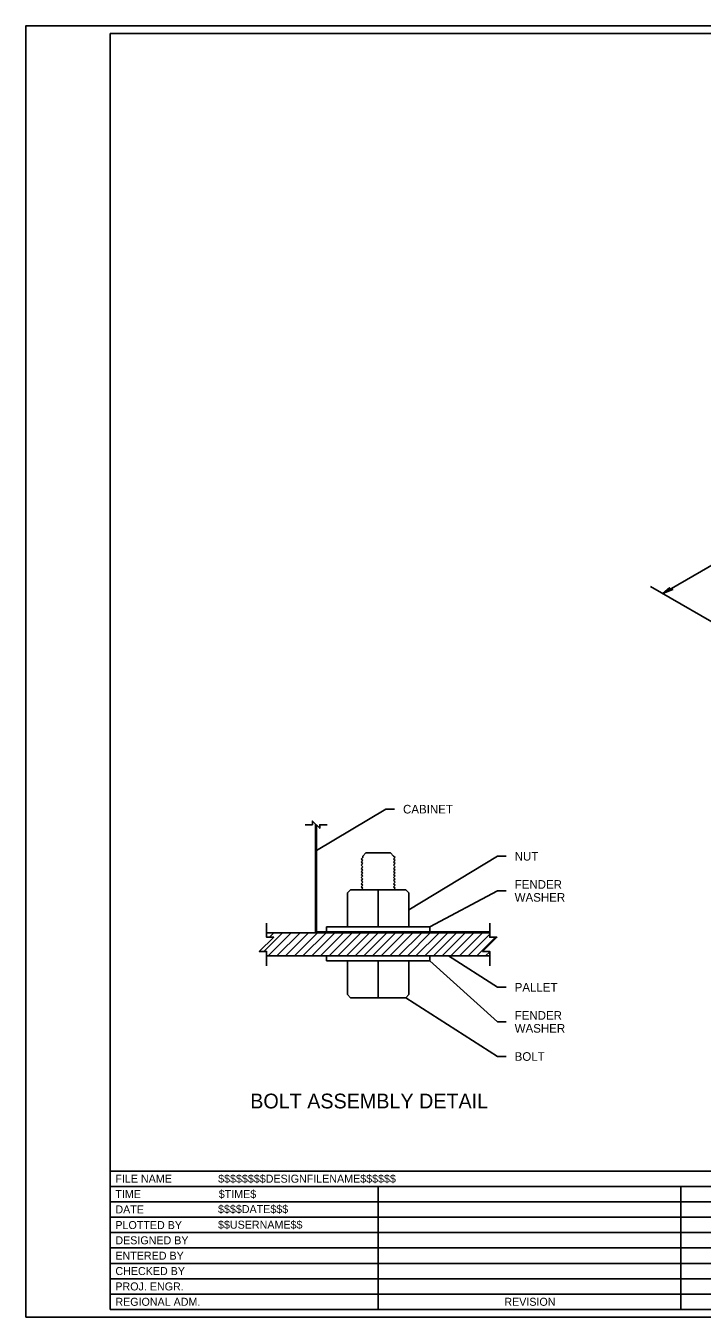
# Model space of a CAD drawing. Extents: x 99988 to 100172, y 99995 to 100047.
# Drawn here: x 99999.31 to 100004.81, y 99999.94 to 100010.44 of the extents above; entities that cross this region are included whole.
import ezdxf

# ---------------------------------------------------------------- set-up
doc = ezdxf.new("R2010")
doc.units = 0
for name, color, linetype in [('Level 1', 7, 'Continuous'), ('Level 15', 7, 'Continuous'), ('Level 2', 7, 'Continuous'), ('Level 20', 7, 'Continuous'), ('SH_GI_PlotLimits', 7, 'Continuous'), ('SH_GI_SheetBorder', 7, 'Continuous'), ('SH_GI_SheetTextInCells', 7, 'Continuous'), ('SH_GI_TitleBlockText', 7, 'Continuous'), ('SH_RS_ConstructionNoteFlag', 7, 'Continuous'), ('SH_RS_DimensionLines', 7, 'Continuous')]:
    doc.layers.add(name, color=color, linetype=linetype)

msp = doc.modelspace()

# ---------------------------------------------------------------- linework, layer by layer
at = {"layer": 'Level 1'}
for p, q in [((100002.241, 100004.068), (100002.311, 100004.068)), ((100003.149, 100003.685), (100003.219, 100003.685)), ((100003.149, 100003.403), (100003.219, 100003.403)), ((100003.149, 100002.62), (100003.219, 100002.62)), ((100003.149, 100002.338), (100003.219, 100002.338)), ((100003.149, 100002.057), (100003.219, 100002.057))]:
    msp.add_line(p, q, dxfattribs=at)
at = {"layer": 'Level 15'}
for p, q in [((100007.322, 100007.455), (100004.493, 100005.822)), ((100004.393, 100005.879), (100005.263, 100005.377))]:
    msp.add_line(p, q, dxfattribs=at)
msp.add_lwpolyline([(100004.493, 100005.822), (100004.575, 100005.853), (100004.558, 100005.859), (100004.548, 100005.869)], close=True, dxfattribs=at)
for points in [[(100001.584, 100003.942), (100001.644, 100003.942), (100001.644, 100003.971), (100001.703, 100003.913), (100001.703, 100003.942), (100001.763, 100003.942)], [(100001.271, 100003.142), (100001.271, 100003.027), (100001.329, 100003.027), (100001.212, 100002.911), (100001.271, 100002.911), (100001.271, 100002.795)], [(100003.086, 100003.142), (100003.086, 100003.027), (100003.145, 100003.027), (100003.028, 100002.911), (100003.086, 100002.911), (100003.086, 100002.795)]]:
    msp.add_lwpolyline(points, dxfattribs=at)
at = {"layer": 'Level 2'}
for p, q in [((100001.668, 100003.062), (100001.668, 100003.947)), ((100001.678, 100003.072), (100001.678, 100003.937)), ((100002.078, 100003.712), (100002.053, 100003.687)), ((100002.053, 100003.687), (100002.053, 100003.675)), ((100002.078, 100003.712), (100002.278, 100003.712)), ((100002.278, 100003.712), (100002.303, 100003.687)), ((100002.303, 100003.687), (100002.316, 100003.675)), ((100002.053, 100003.675), (100002.041, 100003.662)), ((100002.041, 100003.662), (100002.053, 100003.65)), ((100002.053, 100003.65), (100002.041, 100003.637)), ((100002.041, 100003.637), (100002.053, 100003.625)), ((100002.053, 100003.625), (100002.041, 100003.612)), ((100002.041, 100003.612), (100002.053, 100003.6)), ((100002.053, 100003.6), (100002.041, 100003.587)), ((100002.041, 100003.587), (100002.053, 100003.575)), ((100002.053, 100003.6), (100002.053, 100003.6)), ((100002.316, 100003.675), (100002.303, 100003.662)), ((100002.303, 100003.662), (100002.316, 100003.65)), ((100002.316, 100003.65), (100002.303, 100003.637)), ((100002.303, 100003.637), (100002.316, 100003.625)), ((100002.316, 100003.625), (100002.303, 100003.612)), ((100002.303, 100003.612), (100002.303, 100003.612)), ((100002.303, 100003.612), (100002.316, 100003.6)), ((100002.316, 100003.6), (100002.303, 100003.587)), ((100002.303, 100003.587), (100002.316, 100003.575)), ((100002.053, 100003.575), (100002.041, 100003.562)), ((100002.041, 100003.562), (100002.053, 100003.55)), ((100002.053, 100003.55), (100002.041, 100003.537)), ((100002.041, 100003.537), (100002.053, 100003.525)), ((100002.053, 100003.525), (100002.041, 100003.512)), ((100002.041, 100003.512), (100002.053, 100003.5)), ((100002.053, 100003.5), (100002.041, 100003.487)), ((100002.041, 100003.487), (100002.053, 100003.475)), ((100002.053, 100003.475), (100002.041, 100003.462)), ((100002.316, 100003.575), (100002.303, 100003.562)), ((100002.303, 100003.562), (100002.316, 100003.55)), ((100002.316, 100003.55), (100002.303, 100003.537)), ((100002.303, 100003.537), (100002.316, 100003.525)), ((100002.316, 100003.525), (100002.303, 100003.512)), ((100002.303, 100003.512), (100002.316, 100003.5)), ((100002.316, 100003.5), (100002.303, 100003.487)), ((100002.303, 100003.487), (100002.316, 100003.475)), ((100002.316, 100003.475), (100002.303, 100003.462)), ((100001.953, 100003.412), (100001.928, 100003.387)), ((100001.928, 100003.112), (100001.928, 100003.387)), ((100001.953, 100003.412), (100002.403, 100003.412)), ((100002.041, 100003.462), (100002.053, 100003.45)), ((100002.053, 100003.45), (100002.041, 100003.437)), ((100002.041, 100003.437), (100002.053, 100003.425)), ((100002.053, 100003.425), (100002.041, 100003.412)), ((100002.178, 100003.112), (100002.178, 100003.412)), ((100002.303, 100003.462), (100002.316, 100003.45)), ((100002.316, 100003.45), (100002.303, 100003.437)), ((100002.303, 100003.437), (100002.316, 100003.425)), ((100002.316, 100003.425), (100002.303, 100003.412)), ((100002.403, 100003.412), (100002.428, 100003.387)), ((100002.428, 100003.112), (100002.428, 100003.387)), ((100001.249, 100002.911), (100001.401, 100003.062)), ((100001.271, 100003.062), (100003.086, 100003.062)), ((100001.284, 100002.875), (100001.472, 100003.062)), ((100001.295, 100003.027), (100001.33, 100003.062)), ((100001.355, 100002.875), (100001.543, 100003.062)), ((100001.426, 100002.875), (100001.613, 100003.062)), ((100001.497, 100002.875), (100001.684, 100003.062)), ((100001.567, 100002.875), (100001.755, 100003.062)), ((100001.638, 100002.875), (100001.825, 100003.062)), ((100001.678, 100003.072), (100003.086, 100003.072)), ((100001.709, 100002.875), (100001.896, 100003.062)), ((100001.758, 100003.072), (100001.758, 100003.112)), ((100002.598, 100003.112), (100001.758, 100003.112)), ((100001.779, 100002.875), (100001.967, 100003.062)), ((100001.85, 100002.875), (100002.038, 100003.062)), ((100001.921, 100002.875), (100002.108, 100003.062)), ((100002.403, 100003.112), (100001.953, 100003.112)), ((100001.992, 100002.875), (100002.179, 100003.062)), ((100002.062, 100002.875), (100002.25, 100003.062)), ((100002.133, 100002.875), (100002.32, 100003.062)), ((100002.204, 100002.875), (100002.391, 100003.062)), ((100002.274, 100002.875), (100002.462, 100003.062)), ((100002.345, 100002.875), (100002.533, 100003.062)), ((100002.416, 100002.875), (100002.603, 100003.062)), ((100002.486, 100002.875), (100002.674, 100003.062)), ((100002.557, 100002.875), (100002.745, 100003.062)), ((100002.598, 100003.072), (100002.598, 100003.112)), ((100002.628, 100002.875), (100002.815, 100003.062)), ((100002.699, 100002.875), (100002.886, 100003.062)), ((100002.769, 100002.875), (100002.957, 100003.062)), ((100002.84, 100002.875), (100003.028, 100003.062)), ((100002.911, 100002.875), (100003.086, 100003.051)), ((100002.981, 100002.875), (100003.133, 100003.027)), ((100001.271, 100002.875), (100003.086, 100002.875)), ((100001.758, 100002.875), (100001.758, 100002.835)), ((100002.598, 100002.875), (100002.598, 100002.835)), ((100003.052, 100002.875), (100003.086, 100002.909)), ((100002.598, 100002.835), (100001.758, 100002.835)), ((100001.928, 100002.835), (100001.928, 100002.56)), ((100002.178, 100002.535), (100002.178, 100002.835)), ((100002.428, 100002.835), (100002.428, 100002.56)), ((100001.953, 100002.535), (100001.928, 100002.56)), ((100001.953, 100002.535), (100002.403, 100002.535)), ((100002.428, 100002.56), (100002.403, 100002.535))]:
    msp.add_line(p, q, dxfattribs=at)
at = {"layer": 'SH_GI_PlotLimits'}
msp.add_lwpolyline([(99999.312, 99999.937), (100015.812, 99999.937), (100015.812, 100010.437), (99999.312, 100010.437)], close=True, dxfattribs=at)
at = {"layer": 'SH_GI_SheetBorder'}
for p, q in [((100000, 100010.375), (100000, 100000)), ((100000, 100010.375), (100015.75, 100010.375)), ((100000, 100001.126), (100015.75, 100001.126)), ((100000, 100001.001), (100007.457, 100001.001)), ((100002.179, 100001.001), (100002.179, 100000)), ((100004.641, 100001.001), (100004.641, 100000)), ((100000, 100000.876), (100002.182, 100000.876)), ((100002.182, 100000.876), (100005.447, 100000.876)), ((100000, 100000.751), (100002.182, 100000.751)), ((100002.182, 100000.751), (100005.447, 100000.751)), ((100000, 100000.625), (100005.447, 100000.625)), ((100000, 100000.5), (100005.447, 100000.5)), ((100000, 100000.375), (100005.447, 100000.375)), ((100000, 100000.25), (100005.447, 100000.25)), ((100000, 100000.125), (100005.447, 100000.125)), ((100000, 100000), (100015.75, 100000))]:
    msp.add_line(p, q, dxfattribs=at)
at = {"layer": 'SH_RS_DimensionLines'}
for p, q in [((100001.678, 100003.731), (100002.241, 100004.068)), ((100002.428, 100003.25), (100003.149, 100003.685)), ((100002.598, 100003.112), (100003.149, 100003.403)), ((100002.752, 100002.875), (100003.149, 100002.62)), ((100002.598, 100002.835), (100003.149, 100002.338)), ((100002.403, 100002.535), (100003.149, 100002.057))]:
    msp.add_line(p, q, dxfattribs=at)

# ---------------------------------------------------------------- texts
at = {"layer": 'Level 20'}
msp.add_text('BOLT ASSEMBLY DETAIL', height=0.12, dxfattribs=at).set_placement((100001.138, 100001.635))
at = {"layer": 'SH_GI_SheetTextInCells'}
for s, height, p in [('FILE NAME', 0.0651, (100000.041, 100001.031)), ('TIME', 0.0651, (100000.041, 100000.906)), ('DATE', 0.0651, (100000.041, 100000.781)), ('PLOTTED BY', 0.0651, (100000.041, 100000.654)), ('DESIGNED BY', 0.06505, (100000.041, 100000.53)), ('ENTERED BY', 0.0651, (100000.041, 100000.405)), ('CHECKED BY', 0.0651, (100000.041, 100000.28)), ('PROJ. ENGR.', 0.06505, (100000.041, 100000.155)), ('REGIONAL ADM.', 0.06505, (100000.041, 100000.03)), ('REVISION', 0.0651, (100003.205, 100000.03))]:
    msp.add_text(s, height=height, dxfattribs=at).set_placement(p)
at = {"layer": 'SH_GI_TitleBlockText'}
for s, height, p in [('$$$$$$$$DESIGNFILENAME$$$$$$', 0.06505, (100000.877, 100001.031)), ('$TIME$', 0.0651, (100000.882, 100000.906)), ('$$$$DATE$$$', 0.06505, (100000.876, 100000.784)), ('$$USERNAME$$', 0.06505, (100000.876, 100000.657))]:
    msp.add_text(s, height=height, dxfattribs=at).set_placement(p)
at = {"layer": 'SH_RS_ConstructionNoteFlag'}
for s, p in [('CABINET', (100002.381, 100004.033)), ('NUT', (100003.289, 100003.65)), ('FENDER', (100003.289, 100003.421)), ('WASHER', (100003.289, 100003.316)), ('PALLET', (100003.289, 100002.585)), ('FENDER', (100003.289, 100002.356)), ('WASHER', (100003.289, 100002.251)), ('BOLT', (100003.289, 100002.022))]:
    msp.add_text(s, height=0.07, rotation=360, dxfattribs=at).set_placement(p)

doc.saveas('drawing.dxf')
